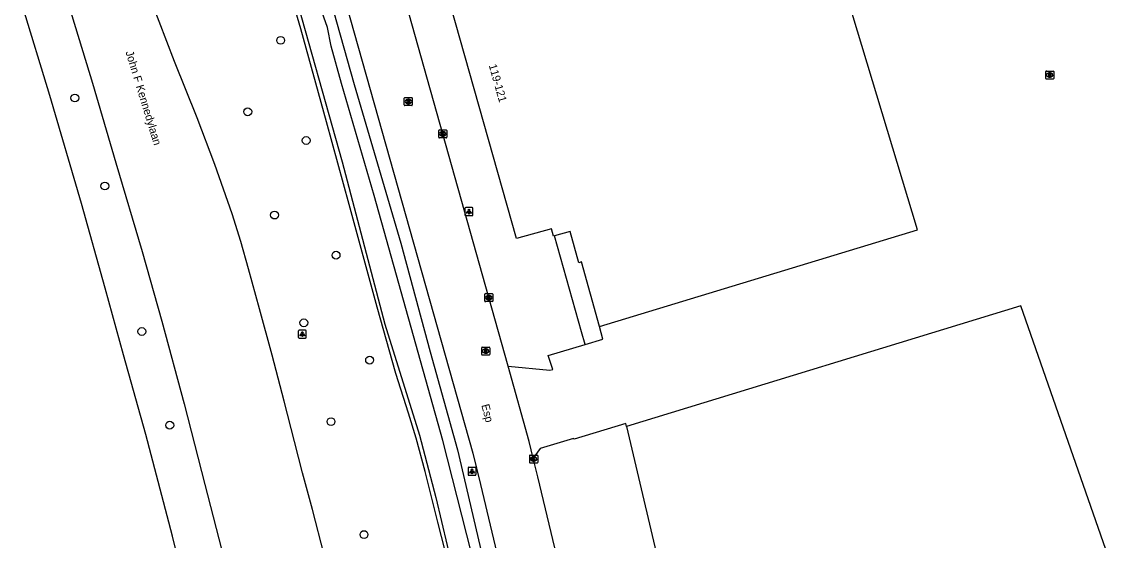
# Model space of a CAD drawing. Extents: x 161389 to 162585, y 388479 to 389761.
# Drawn here: x 162041.7 to 162179.6, y 388585.3 to 388650.1 of the extents above; entities that cross this region are included whole.
import ezdxf

# ---------------------------------------------------------------- set-up
doc = ezdxf.new("R2010")
doc.units = 0
for name, color, linetype in [('IMGEO_Berm_groen', 7, 'Continuous'), ('IMGEO_Boom', 7, 'Continuous'), ('IMGEO_Groenvoorziening', 7, 'Continuous'), ('IMGEO_Hek', 7, 'Continuous'), ('IMGEO_Kolk', 7, 'Continuous'), ('IMGEO_Lichtpunt', 7, 'Continuous'), ('IMGEO_Openbare_ruimte_label', 7, 'Continuous'), ('IMGEO_Pand', 7, 'Continuous'), ('IMGEO_Pand_nummerreeks', 7, 'Continuous'), ('IMGEO_Rijbaan_autoweg', 7, 'Continuous'), ('IMGEO_Rijbaan_lokaal_gesloten', 7, 'Continuous'), ('IMGEO_Rioolput', 7, 'Continuous'), ('IMGEO_Voetpad_open', 7, 'Continuous'), ('IMGEO_Waterloop', 7, 'Continuous')]:
    doc.layers.add(name, color=color, linetype=linetype)

msp = doc.modelspace()

# ---------------------------------------------------------------- linework, layer by layer
at = {"layer": 'IMGEO_Berm_groen'}
msp.add_lwpolyline([(162107.35, 388529.17), (162107.02, 388530.28), (162104.55, 388540.61), (162101.39, 388555.57), (162100.19, 388560.43), (162099.86, 388561.15), (162099.32, 388562.04), (162098.59, 388563.02), (162098.09, 388563.91), (162097.99, 388564.55), (162097.98, 388565.43), (162098.21, 388566.64), (162098.21, 388568.23), (162096.72, 388575.57), (162093.64, 388587.62), (162092.04, 388593.96), (162090.95, 388598.12), (162089.96, 388601.22), (162088.37, 388606.18), (162086.05, 388614.47), (162082.57, 388627.3), (162079.72, 388637.61), (162076.52, 388649.23), (162074.93, 388654.62)], dxfattribs=at)
at = {"layer": 'IMGEO_Boom'}
for centre in [(162073.99, 388647.78), (162048.27, 388640.58), (162069.88, 388638.86), (162077.18, 388635.27), (162052.02, 388629.59), (162073.23, 388625.96), (162080.92, 388620.95), (162076.89, 388612.51), (162056.64, 388611.42), (162085.11, 388607.85), (162060.13, 388599.72), (162080.29, 388600.17), (162084.41, 388586.06)]:
    msp.add_circle(centre, 0.489, dxfattribs=at)
at = {"layer": 'IMGEO_Groenvoorziening'}
for points in [[(162075.2, 388671.89), (162075.47, 388671.69), (162075.79, 388671.06), (162075.96, 388670.35), (162076.05, 388669.51), (162075.99, 388668.7), (162075.89, 388668.02), (162076.09, 388667.06), (162078.83, 388657.67), (162083.2, 388642.27), (162089, 388622.46), (162092.68, 388608.87), (162096.11, 388596.65), (162100.06, 388579.7), (162104.07, 388563.88), (162108.26, 388546.31), (162110.15, 388538.02), (162111.76, 388531.78), (162111.82, 388531.42)], [(162102.41, 388607.11), (162107.65, 388606.58), (162108, 388606.67), (162107.45, 388608.41), (162112.04, 388609.8)], [(162117.23, 388599.58), (162117.15, 388599.92), (162110.66, 388597.96), (162110.58, 388598.07), (162106.44, 388596.8), (162105.57, 388595.61)]]:
    msp.add_lwpolyline(points, dxfattribs=at)
at = {"layer": 'IMGEO_Hek'}
msp.add_lwpolyline([(162117.15, 388599.92), (162110.66, 388597.96)], dxfattribs=at)
at = {"layer": 'IMGEO_Kolk'}
for p, q in [((162093.76, 388635.67), (162093.76, 388636.53)), ((162093.83, 388636.6), (162094.68, 388636.6)), ((162094.68, 388635.6), (162093.83, 388635.6)), ((162094.24, 388636.38), (162094.27, 388636.38)), ((162094.27, 388635.82), (162094.24, 388635.82)), ((162094.76, 388636.53), (162094.76, 388635.67)), ((162099.51, 388615.22), (162099.51, 388616.07)), ((162099.58, 388616.15), (162100.44, 388616.15)), ((162100.44, 388615.15), (162099.58, 388615.15)), ((162100.02, 388615.37), (162099.99, 388615.37)), ((162100, 388615.93), (162100.02, 388615.93)), ((162100.51, 388616.07), (162100.51, 388615.22)), ((162105.12, 388595.07), (162105.12, 388595.92)), ((162105.19, 388596), (162106.04, 388596)), ((162105.6, 388595.78), (162105.63, 388595.78)), ((162106.12, 388595.92), (162106.12, 388595.07)), ((162106.04, 388595), (162105.19, 388595)), ((162105.63, 388595.22), (162105.6, 388595.22))]:
    msp.add_line(p, q, dxfattribs=at)
for points in [[(162093.76, 388635.67), (162093.76, 388636.53)], [(162093.83, 388636.6), (162094.68, 388636.6)], [(162094.68, 388635.6), (162093.83, 388635.6)], [(162094.08, 388636.3), (162094.2, 388636.3), (162094.2, 388636.15), (162094.33, 388636.3), (162094.49, 388636.3), (162094.35, 388636.15), (162094.5, 388635.9), (162094.35, 388635.9), (162094.26, 388636.06), (162094.2, 388636), (162094.2, 388635.9), (162094.08, 388635.9), (162094.08, 388636.3)], [(162094.76, 388636.53), (162094.76, 388635.67)], [(162099.51, 388615.22), (162099.51, 388616.07)], [(162099.58, 388616.15), (162100.44, 388616.15)], [(162100.44, 388615.15), (162099.58, 388615.15)], [(162099.83, 388615.85), (162099.95, 388615.85), (162099.95, 388615.7), (162100.08, 388615.85), (162100.25, 388615.85), (162100.1, 388615.7), (162100.25, 388615.45), (162100.1, 388615.45), (162100.02, 388615.61), (162099.95, 388615.55), (162099.95, 388615.45), (162099.83, 388615.45), (162099.83, 388615.85)], [(162100.51, 388616.07), (162100.51, 388615.22)], [(162105.12, 388595.07), (162105.12, 388595.92)], [(162105.19, 388596), (162106.04, 388596)], [(162105.44, 388595.7), (162105.56, 388595.7), (162105.56, 388595.54), (162105.69, 388595.7), (162105.85, 388595.7), (162105.71, 388595.55), (162105.86, 388595.3), (162105.71, 388595.3), (162105.62, 388595.46), (162105.56, 388595.39), (162105.56, 388595.3), (162105.44, 388595.3), (162105.44, 388595.7)], [(162106.12, 388595.92), (162106.12, 388595.07)], [(162106.04, 388595), (162105.19, 388595)]]:
    msp.add_lwpolyline(points, dxfattribs=at)
for centre, start, end in [((162093.83, 388636.52), 91.552, 178.448), ((162093.83, 388636.52), 91.552, 178.448), ((162093.83, 388635.68), 181.552, 268.448), ((162093.83, 388635.68), 181.552, 268.448), ((162094.68, 388636.52), 1.552, 88.448), ((162094.68, 388636.52), 1.552, 88.448), ((162094.68, 388635.68), 271.552, 358.448), ((162094.68, 388635.68), 271.552, 358.448), ((162099.58, 388616.07), 91.552, 178.448), ((162099.58, 388616.07), 91.552, 178.448), ((162099.58, 388615.22), 181.552, 268.448), ((162099.58, 388615.22), 181.552, 268.448), ((162100.43, 388616.07), 1.552, 88.448), ((162100.43, 388616.07), 1.552, 88.448), ((162100.43, 388615.22), 271.552, 358.448), ((162100.43, 388615.22), 271.552, 358.448), ((162105.19, 388595.92), 91.552, 178.448), ((162105.19, 388595.92), 91.552, 178.448), ((162106.04, 388595.92), 1.552, 88.448), ((162106.04, 388595.92), 1.552, 88.448), ((162105.19, 388595.07), 181.552, 268.448), ((162105.19, 388595.07), 181.552, 268.448), ((162106.04, 388595.07), 271.552, 358.448), ((162106.04, 388595.07), 271.552, 358.448)]:
    msp.add_arc(centre, 0.0765, start, end, dxfattribs=at)
for centre, major_axis, ratio, start_param, end_param in [((162094.24, 388636.1), (-0.387, 0.002), 0.722429, 4.712389, 7.853982), ((162094.27, 388636.1), (-0.39, 0.002), 0.717154, 1.570796, 4.712389), ((162100, 388615.65), (-0.387, 0.002), 0.722429, 4.712389, 7.853982), ((162100.02, 388615.65), (-0.39, 0.002), 0.717154, 1.570796, 4.712389), ((162105.6, 388595.5), (-0.387, 0.002), 0.722429, 4.712389, 7.853982), ((162105.63, 388595.5), (-0.39, 0.002), 0.717154, 1.570796, 4.712389)]:
    msp.add_ellipse(centre, major_axis=major_axis, ratio=ratio, start_param=start_param, end_param=end_param, dxfattribs=at)
at = {"layer": 'IMGEO_Lichtpunt'}
for p, q in [((162097.03, 388626.8), (162097.03, 388625.99)), ((162097.03, 388626.8), (162097.03, 388625.99)), ((162097.93, 388626.9), (162097.12, 388626.9)), ((162097.93, 388626.9), (162097.12, 388626.9)), ((162098.02, 388625.99), (162098.02, 388626.8)), ((162098.02, 388625.99), (162098.02, 388626.8)), ((162097.12, 388625.9), (162097.93, 388625.9)), ((162097.12, 388625.9), (162097.93, 388625.9)), ((162076.2, 388611.49), (162076.2, 388610.69)), ((162076.2, 388611.49), (162076.2, 388610.69)), ((162077.1, 388611.59), (162076.3, 388611.59)), ((162077.1, 388611.59), (162076.3, 388611.59)), ((162077.2, 388610.69), (162077.2, 388611.49)), ((162077.2, 388610.69), (162077.2, 388611.49)), ((162076.3, 388610.59), (162077.1, 388610.59)), ((162076.3, 388610.59), (162077.1, 388610.59)), ((162097.41, 388594.37), (162097.41, 388593.56)), ((162097.41, 388594.37), (162097.41, 388593.56)), ((162098.31, 388594.46), (162097.51, 388594.46)), ((162098.31, 388594.46), (162097.51, 388594.46)), ((162098.41, 388593.56), (162098.41, 388594.37)), ((162098.41, 388593.56), (162098.41, 388594.37)), ((162097.51, 388593.47), (162098.31, 388593.47)), ((162097.51, 388593.47), (162098.31, 388593.47))]:
    msp.add_line(p, q, dxfattribs=at)
for points in [[(162097.4, 388626.46), (162097.44, 388626.44), (162097.25, 388626.17), (162097.21, 388626.2), (162097.4, 388626.46)], [(162097.5, 388626.42), (162097.55, 388626.42), (162097.55, 388626.09), (162097.5, 388626.09), (162097.5, 388626.42)], [(162097.61, 388626.44), (162097.65, 388626.46), (162097.84, 388626.2), (162097.8, 388626.17), (162097.61, 388626.44)], [(162076.58, 388611.16), (162076.61, 388611.13), (162076.43, 388610.87), (162076.39, 388610.89), (162076.58, 388611.16)], [(162076.68, 388611.11), (162076.73, 388611.11), (162076.73, 388610.79), (162076.68, 388610.79), (162076.68, 388611.11)], [(162076.79, 388611.13), (162076.83, 388611.16), (162077.01, 388610.89), (162076.97, 388610.87), (162076.79, 388611.13)], [(162097.79, 388594.03), (162097.83, 388594), (162097.64, 388593.74), (162097.6, 388593.77), (162097.79, 388594.03)], [(162097.89, 388593.98), (162097.94, 388593.98), (162097.94, 388593.66), (162097.89, 388593.66), (162097.89, 388593.98)], [(162098, 388594), (162098.04, 388594.03), (162098.22, 388593.77), (162098.19, 388593.74), (162098, 388594)]]:
    msp.add_lwpolyline(points, dxfattribs=at)
for centre in [(162097.53, 388626.6), (162076.7, 388611.29), (162097.91, 388594.17)]:
    msp.add_circle(centre, 0.0994, dxfattribs=at)
for centre, start, end in [((162097.12, 388626.8), 90, 180), ((162097.12, 388626.8), 90, 180), ((162097.12, 388625.99), 180, 270), ((162097.12, 388625.99), 180, 270), ((162097.93, 388626.8), 0, 90), ((162097.93, 388626.8), 0, 90), ((162097.93, 388625.99), 270, 0), ((162097.93, 388625.99), 270, 360), ((162076.3, 388611.49), 90, 180), ((162076.3, 388611.49), 90, 180), ((162077.1, 388611.49), 0, 90), ((162077.1, 388611.49), 0, 90), ((162076.3, 388610.69), 180, 270), ((162076.3, 388610.69), 180, 270), ((162077.1, 388610.69), 270, 0), ((162077.1, 388610.69), 270, 360), ((162097.51, 388594.37), 90, 180), ((162097.51, 388594.37), 90, 180), ((162098.31, 388594.37), 0, 90), ((162098.31, 388594.37), 0, 90), ((162097.51, 388593.56), 180, 270), ((162097.51, 388593.56), 180, 270), ((162098.31, 388593.56), 270, 0), ((162098.31, 388593.56), 270, 360)]:
    msp.add_arc(centre, 0.0946, start, end, dxfattribs=at)
at = {"layer": 'IMGEO_Pand'}
for points in [[(162108.23, 388623.36), (162108.09, 388623.32), (162107.86, 388624.25), (162103.49, 388623.05), (162093.53, 388658.24), (162100.3, 388660.15), (162098.26, 388666.85), (162119.52, 388673.29)], [(162113.85, 388612.03), (162153.61, 388624.13), (162139.15, 388671.98)], [(162113.85, 388612.03), (162111.58, 388620.11), (162111.27, 388620), (162110.18, 388623.89), (162108.23, 388623.36)], [(162172.77, 388552.84), (162167.71, 388574.1), (162179.65, 388577.03), (162166.51, 388614.64), (162117.23, 388599.58)], [(162117.23, 388599.58), (162122.08, 388578.89), (162115.31, 388577.3), (162124.8, 388536.79)]]:
    msp.add_lwpolyline(points, dxfattribs=at)
at = {"layer": 'IMGEO_Rijbaan_autoweg'}
for points in [[(162078.51, 388508.24), (162075.87, 388520.19), (162073.31, 388532.1), (162071.12, 388541.84), (162068.51, 388552.88), (162066.69, 388560.96), (162063.26, 388574.46), (162060.49, 388585.85), (162057.13, 388598.56), (162054.33, 388608.5), (162052.04, 388616.85), (162049.09, 388627.42), (162045.12, 388640.89), (162041.67, 388652.21)], [(162047.42, 388652.39), (162050.48, 388642.45), (162053.41, 388632.5), (162056.68, 388621.43), (162059.14, 388612.7), (162061.92, 388602.39), (162064.52, 388592.31), (162066.98, 388582.79), (162068.93, 388575.2), (162070.71, 388568.2), (162072.99, 388559.32), (162074.04, 388555.21), (162075.47, 388552.32), (162075.58, 388552.01), (162077.16, 388545.13), (162078.39, 388539.68), (162079.34, 388535.42), (162080.35, 388530.78), (162081.44, 388525.99), (162082.83, 388519.3), (162083.82, 388514.48), (162084.67, 388510.35)], [(162079.43, 388583.53), (162077.96, 388589.21), (162076.74, 388593.77), (162075.73, 388597.68), (162074.43, 388602.73), (162072.92, 388608.46), (162071.33, 388614.27), (162069.99, 388619.24), (162069.02, 388622.67), (162067.92, 388626.13), (162065.76, 388632.28), (162063.54, 388638.1), (162060.74, 388645.12), (162057.84, 388652.62)]]:
    msp.add_lwpolyline(points, dxfattribs=at)
at = {"layer": 'IMGEO_Rijbaan_lokaal_gesloten'}
for points in [[(162094.96, 388678.66), (162093.24, 388677.97), (162091.58, 388677.12), (162090.02, 388676.13), (162088.54, 388675.01), (162087.17, 388673.75), (162085.92, 388672.38), (162084.79, 388670.91), (162083.81, 388669.34), (162082.96, 388667.68), (162082.27, 388665.96), (162081.73, 388664.18), (162081.36, 388662.37), (162081.15, 388660.52), (162081.1, 388658.67), (162081.22, 388656.81), (162081.51, 388654.98), (162081.74, 388653.94), (162098, 388596.21), (162098.98, 388592.32), (162113.11, 388532.98)], [(162102.41, 388607.11), (162100.01, 388615.65), (162088.88, 388655.2)], [(162105.57, 388595.61), (162105.07, 388597.69), (162102.41, 388607.11)], [(162120.01, 388535.05), (162119.59, 388536.79), (162114.98, 388556.23), (162110.38, 388575.54), (162106.15, 388593.26), (162105.57, 388595.61)]]:
    msp.add_lwpolyline(points, dxfattribs=at)
at = {"layer": 'IMGEO_Rioolput'}
for p, q in [((162169.62, 388643.03), (162169.62, 388643.88)), ((162169.69, 388643.95), (162170.55, 388643.95)), ((162170.62, 388643.88), (162170.62, 388643.03)), ((162170.55, 388642.95), (162169.69, 388642.95)), ((162170.11, 388643.73), (162170.13, 388643.73)), ((162170.13, 388643.17), (162170.11, 388643.17)), ((162089.45, 388639.71), (162089.45, 388640.56)), ((162089.52, 388640.64), (162090.38, 388640.64)), ((162089.96, 388639.86), (162089.93, 388639.86)), ((162089.94, 388640.42), (162089.96, 388640.42)), ((162090.45, 388640.56), (162090.45, 388639.71)), ((162090.38, 388639.64), (162089.52, 388639.64)), ((162099.12, 388608.55), (162099.12, 388609.4)), ((162099.19, 388609.48), (162100.05, 388609.48)), ((162100.12, 388609.4), (162100.12, 388608.55)), ((162100.05, 388608.48), (162099.19, 388608.48)), ((162099.61, 388609.26), (162099.63, 388609.26)), ((162099.63, 388608.7), (162099.61, 388608.7))]:
    msp.add_line(p, q, dxfattribs=at)
for points in [[(162169.62, 388643.03), (162169.62, 388643.88)], [(162169.69, 388643.95), (162170.55, 388643.95)], [(162170.62, 388643.88), (162170.62, 388643.03)], [(162170.55, 388642.95), (162169.69, 388642.95)], [(162170.21, 388643.65), (162169.96, 388643.65), (162169.96, 388643.25)], [(162169.96, 388643.25), (162170.08, 388643.25), (162170.08, 388643.42), (162170.09, 388643.42)], [(162170.14, 388643.57), (162170.08, 388643.57), (162170.08, 388643.49)], [(162170.08, 388643.49), (162170.13, 388643.49)], [(162170.14, 388643.39), (162170.21, 388643.25), (162170.35, 388643.25), (162170.28, 388643.38)], [(162089.45, 388639.71), (162089.45, 388640.56)], [(162089.52, 388640.64), (162090.38, 388640.64)], [(162090.04, 388640.33), (162089.78, 388640.34), (162089.78, 388639.94)], [(162089.78, 388639.94), (162089.91, 388639.94), (162089.91, 388640.1), (162089.92, 388640.1)], [(162089.96, 388640.26), (162089.91, 388640.26), (162089.91, 388640.17)], [(162089.91, 388640.17), (162089.96, 388640.17)], [(162089.97, 388640.07), (162090.04, 388639.94), (162090.18, 388639.94), (162090.11, 388640.06)], [(162090.45, 388640.56), (162090.45, 388639.71)], [(162090.38, 388639.64), (162089.52, 388639.64)], [(162099.12, 388608.55), (162099.12, 388609.4)], [(162099.19, 388609.48), (162100.05, 388609.48)], [(162100.12, 388609.4), (162100.12, 388608.55)], [(162100.05, 388608.48), (162099.19, 388608.48)], [(162099.71, 388609.18), (162099.46, 388609.18), (162099.46, 388608.78)], [(162099.46, 388608.78), (162099.58, 388608.78), (162099.58, 388608.94), (162099.59, 388608.94)], [(162099.64, 388609.1), (162099.58, 388609.1), (162099.58, 388609.02)], [(162099.58, 388609.02), (162099.63, 388609.02)], [(162099.64, 388608.91), (162099.71, 388608.78), (162099.85, 388608.78), (162099.78, 388608.9)]]:
    msp.add_lwpolyline(points, dxfattribs=at)
for centre, radius, start, end in [((162169.7, 388643.88), 0.0765, 91.552, 178.448), ((162169.7, 388643.88), 0.0765, 91.552, 178.448), ((162170.54, 388643.88), 0.0765, 1.552, 88.448), ((162170.54, 388643.88), 0.0765, 1.552, 88.448), ((162169.7, 388643.03), 0.0765, 181.552, 268.448), ((162169.7, 388643.03), 0.0765, 181.552, 268.448), ((162170.09, 388643.36), 0.0533, 26.0293, 88.6989), ((162170.12, 388643.68), 0.19, 274.7715, 282.9687), ((162170.14, 388643.48), 0.0964, 77.0061, 93.1865), ((162170.16, 388643.53), 0.0378, 276.6634, 79.6772), ((162170.21, 388643.54), 0.109, 350.3612, 89.416), ((162170.21, 388643.54), 0.112, 277.5842, 350.9817), ((162170.19, 388643.33), 0.108, 29.5134, 73.7905), ((162170.54, 388643.03), 0.0765, 271.552, 358.448), ((162170.54, 388643.03), 0.0765, 271.552, 358.448), ((162089.52, 388640.56), 0.0765, 91.552, 178.448), ((162089.52, 388640.56), 0.0765, 91.552, 178.448), ((162089.52, 388639.71), 0.0765, 181.552, 268.448), ((162089.52, 388639.71), 0.0765, 181.552, 268.448), ((162089.92, 388640.05), 0.0533, 26.0293, 88.6989), ((162089.97, 388640.16), 0.0964, 77.0061, 93.1865), ((162089.95, 388640.36), 0.19, 274.7715, 282.9687), ((162089.98, 388640.22), 0.0378, 276.6634, 79.6772), ((162090.04, 388640.22), 0.109, 350.3612, 89.416), ((162090.03, 388640.22), 0.112, 277.5842, 350.9817), ((162090.02, 388640.01), 0.108, 29.5134, 73.7905), ((162090.37, 388640.56), 0.0765, 1.552, 88.448), ((162090.37, 388640.56), 0.0765, 1.552, 88.448), ((162090.37, 388639.71), 0.0765, 271.552, 358.448), ((162090.37, 388639.71), 0.0765, 271.552, 358.448), ((162099.2, 388609.4), 0.0765, 91.552, 178.448), ((162099.2, 388609.4), 0.0765, 91.552, 178.448), ((162100.04, 388609.4), 0.0765, 1.552, 88.448), ((162100.04, 388609.4), 0.0765, 1.552, 88.448), ((162099.2, 388608.55), 0.0765, 181.552, 268.448), ((162099.2, 388608.55), 0.0765, 181.552, 268.448), ((162099.59, 388608.89), 0.0533, 26.0293, 88.6989), ((162099.62, 388609.21), 0.19, 274.7715, 282.9687), ((162099.64, 388609), 0.0964, 77.0061, 93.1865), ((162099.66, 388609.06), 0.0378, 276.6634, 79.6772), ((162099.71, 388609.07), 0.109, 350.3612, 89.416), ((162099.71, 388609.07), 0.112, 277.5842, 350.9817), ((162099.69, 388608.85), 0.108, 29.5134, 73.7905), ((162100.04, 388608.55), 0.0765, 271.552, 358.448), ((162100.04, 388608.55), 0.0765, 271.552, 358.448)]:
    msp.add_arc(centre, radius, start, end, dxfattribs=at)
for centre, major_axis, ratio, start_param, end_param in [((162170.11, 388643.45), (-0.387, 0.002), 0.722429, 4.712389, 7.853982), ((162170.13, 388643.45), (-0.39, 0.002), 0.717154, 1.570796, 4.712389), ((162089.94, 388640.14), (-0.387, 0.002), 0.722429, 4.712389, 7.853982), ((162089.96, 388640.14), (-0.39, 0.002), 0.717154, 1.570796, 4.712389), ((162099.61, 388608.98), (-0.387, 0.002), 0.722429, 4.712389, 7.853982), ((162099.63, 388608.98), (-0.39, 0.002), 0.717154, 1.570796, 4.712389)]:
    msp.add_ellipse(centre, major_axis=major_axis, ratio=ratio, start_param=start_param, end_param=end_param, dxfattribs=at)
at = {"layer": 'IMGEO_Voetpad_open'}
for points in [[(162112.04, 388609.8), (162111.6, 388611.39), (162108.23, 388623.36)], [(162112.04, 388609.8), (162114.28, 388610.47), (162113.85, 388612.03)]]:
    msp.add_lwpolyline(points, dxfattribs=at)
at = {"layer": 'IMGEO_Waterloop'}
for points in [[(162109.77, 388529.76), (162110.43, 388530.34), (162110.47, 388530.88), (162105.81, 388550.16), (162104.6, 388555.6), (162097.84, 388583.73), (162094.25, 388597.8), (162085.69, 388628.4), (162081.58, 388642.4), (162080.31, 388647.06), (162079.86, 388649.39), (162078.53, 388653.17), (162074.37, 388667.58), (162074.4, 388668.14), (162074.61, 388668.94), (162074.78, 388669.41), (162075.02, 388669.63), (162074.79, 388670.24), (162073.91, 388670.93), (162073.54, 388671.42), (162072.07, 388674.88)], [(162075.39, 388654.98), (162081.66, 388632.61), (162087.03, 388612.35), (162091.33, 388598.47), (162093.4, 388590.68), (162095.52, 388581.71)]]:
    msp.add_lwpolyline(points, dxfattribs=at)

# ---------------------------------------------------------------- texts
at = {"layer": 'IMGEO_Openbare_ruimte_label'}
for s, rotation, p in [('John F Kennedylaan', 286.9847, (162054.59, 388646.32)), ('Esp', 284.6619, (162099.07, 388602.22))]:
    msp.add_text(s, height=1, rotation=rotation, dxfattribs=at).set_placement(p)
at = {"layer": 'IMGEO_Pand_nummerreeks'}
msp.add_text('119-121', height=1, rotation=285.7962, dxfattribs=at).set_placement((162099.99, 388644.67))

doc.saveas('drawing.dxf')
